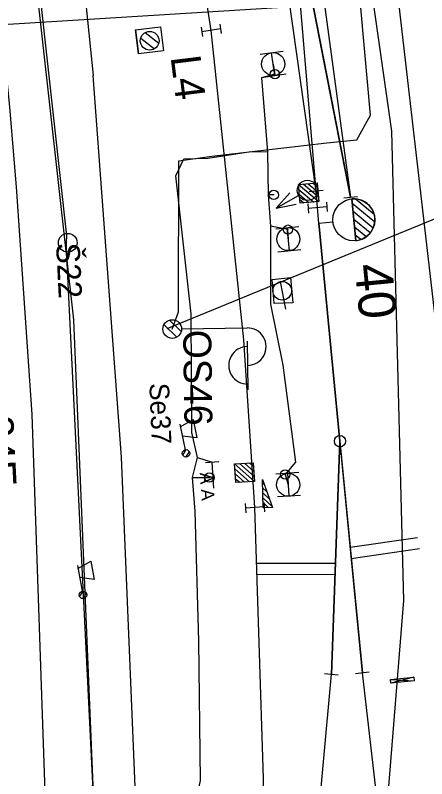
# Model space of a CAD drawing. Extents: x -545736 to -544888, y -1122892 to -1119128.
# Drawn here: x -545114.79 to -545092.81, y -1122018.02 to -1121977.2 of the extents above; entities that cross this region are included whole.
import ezdxf

# ---------------------------------------------------------------- set-up
doc = ezdxf.new("R2010")
doc.units = 0
for name, color, linetype in [('osvětlené plochy-hodnota-obrys', 7, 'Continuous'), ('Vrstva 1', 7, 'Continuous'), ('Vrstva 11 - Trakce', 7, 'Continuous'), ('Vrstva 12 - Trakce zaklady', 7, 'Continuous'), ('Vrstva 2', 7, 'Continuous'), ('Vrstva 25', 7, 'Continuous'), ('Vrstva 26', 7, 'Continuous'), ('Vrstva 27', 7, 'Continuous'), ('Vrstva 28 - zabzar', 7, 'Continuous'), ('Vrstva 3', 7, 'Continuous'), ('Vrstva 3 - Lisy - Pocitaci body', 7, 'Continuous'), ('Vrstva 31', 7, 'Continuous'), ('Vrstva 33', 7, 'Continuous'), ('Vrstva 35', 7, 'Continuous'), ('Vrstva 43', 7, 'Continuous'), ('Vrstva 44', 7, 'Continuous'), ('Vrstva 47', 7, 'Continuous'), ('Vrstva 6 - Navesti', 7, 'Continuous'), ('Vrstva 63', 7, 'Continuous'), ('Vrstva 7', 7, 'Continuous'), ('Vrstva 7 - Namezniky-vystroj', 7, 'Continuous')]:
    doc.layers.add(name, color=color, linetype=linetype)

msp = doc.modelspace()

# ---------------------------------------------------------------- linework, layer by layer
at = {"layer": 'osvětlené plochy-hodnota-obrys'}
for points in [[(-545114.36, -1122142.005), (-545095.834, -1122030.811), (-545094.039, -1122008.497), (-545094.672, -1121983.393), (-545097.737, -1121961.902), (-545099.42, -1121918.553), (-545101.285, -1121870.536), (-545123.71, -1121759.379), (-545130.296, -1121736.567), (-545147.419, -1121693.847), (-545162.352, -1121662.092), (-545176.655, -1121642.604), (-545199.404, -1121614.631), (-545212.209, -1121594.037), (-545225.557, -1121565.516)], [(-545115.194, -1122188.84), (-545115.464, -1122158.52), (-545110.116, -1122078.531), (-545109.516, -1122044.98), (-545111.654, -1121993.485), (-545115.876, -1121955.778), (-545121.955, -1121920.051), (-545160.528, -1121723.806), (-545171.589, -1121690.909), (-545189.933, -1121650.816), (-545214.916, -1121599.46)]]:
    msp.add_lwpolyline(points, dxfattribs=at)
at = {"layer": 'Vrstva 1'}
for p, q in [((-545098.003, -1121981.146), (-545100.055, -1121970.675)), ((-545096.872, -1121986.917), (-545098.003, -1121981.146))]:
    msp.add_line(p, q, dxfattribs=at)
for points in [[(-545113.887, -1121998.538), (-545114.726, -1121986.367), (-545115.084, -1121982.113), (-545116.437, -1121968.628), (-545118.368, -1121953.708), (-545121.658, -1121933.786), (-545126, -1121911.447), (-545130.401, -1121888.923), (-545134.741, -1121866.64), (-545139.463, -1121842.499)], [(-545134.071, -1121845.897), (-545128.577, -1121873.956), (-545119.95, -1121917.752), (-545116.436, -1121936.376), (-545113.726, -1121953.511), (-545111.671, -1121970.139), (-545110.636, -1121980.411)], [(-545105.433, -1122068.234), (-545100.293, -1122037.549), (-545100.056, -1122036.054), (-545097.904, -1122012.428), (-545097.443, -1121999.97), (-545098.568, -1121988.313), (-545098.643, -1121987.484), (-545098.717, -1121986.607), (-545100.055, -1121970.675), (-545101.391, -1121953.551)], [(-545109.904, -1122095.374), (-545105.593, -1122069.199), (-545105.433, -1122068.234), (-545103.019, -1122053.82), (-545101.945, -1122036.704), (-545101.525, -1122017.986), (-545101.985, -1122003.523), (-545102.577, -1121994.549), (-545104.325, -1121978.003), (-545107.499, -1121957.653)], [(-545109.904, -1122095.374), (-545108.096, -1122084.399), (-545107.422, -1122068.991), (-545107.109, -1122051.446), (-545107.678, -1122035.331), (-545108.288, -1122020.588), (-545109.122, -1122000.817), (-545110.636, -1121980.411)], [(-545086.277, -1122094.6), (-545087.736, -1122078.961), (-545089.571, -1122062.994), (-545090.744, -1122054.141), (-545092.357, -1122042.208), (-545094.068, -1122029.354), (-545095.393, -1122019.621), (-545096.247, -1122012.36), (-545098.568, -1121988.313)], [(-545113.063, -1122022.444), (-545113.115, -1122020.779), (-545113.887, -1121998.538)]]:
    msp.add_lwpolyline(points, dxfattribs=at)
at = {"layer": 'Vrstva 11 - Trakce'}
for p, q in [((-545107.849, -1121978.124), (-545107.129, -1121978.686)), ((-545108.085, -1121978.415), (-545107.355, -1121978.985))]:
    msp.add_line(p, q, dxfattribs=at)
msp.add_circle((-545107.61, -1121978.559), 0.5, dxfattribs=at)
at = {"layer": 'Vrstva 12 - Trakce zaklady'}
for p, q in [((-545108.362, -1121977.978), (-545107.026, -1121977.818)), ((-545106.867, -1121979.102), (-545108.202, -1121979.253))]:
    msp.add_line(p, q, dxfattribs=at)
for points in [[(-545108.202, -1121979.253), (-545108.362, -1121977.978), (-545107.026, -1121977.818), (-545106.867, -1121979.102), (-545108.202, -1121979.253)], [(-545107.026, -1121977.818), (-545107.026, -1121977.818), (-545106.867, -1121979.102), (-545106.867, -1121979.102)], [(-545108.362, -1121977.978), (-545108.362, -1121977.978), (-545108.202, -1121979.253), (-545108.202, -1121979.253)]]:
    msp.add_lwpolyline(points, dxfattribs=at)
at = {"layer": 'Vrstva 2'}
for p, q in [((-545098.717, -1121986.607), (-545103.4, -1121953.3)), ((-545101.391, -1121953.551), (-545096.872, -1121986.917)), ((-545098.343, -1121986.575), (-545099.091, -1121986.639)), ((-545097.245, -1121986.951), (-545096.499, -1121986.883)), ((-545096.81, -1121987.013), (-545096.594, -1121989.253)), ((-545096.594, -1121989.253), (-545096.81, -1121987.013)), ((-545095.586, -1121988.257), (-545096.785, -1121987.269)), ((-545095.616, -1121987.843), (-545096.624, -1121987.013)), ((-545095.67, -1121988.576), (-545096.744, -1121987.691)), ((-545095.827, -1121988.836), (-545096.704, -1121988.113)), ((-545098.568, -1121988.313), (-545097.821, -1121988.241)), ((-545096.046, -1121989.044), (-545096.663, -1121988.536)), ((-545096.336, -1121989.194), (-545096.622, -1121988.958)), ((-545097.443, -1121999.97), (-545096.247, -1122012.36)), ((-545098.277, -1122012.394), (-545097.531, -1122012.462)), ((-545095.875, -1122012.316), (-545096.619, -1122012.404))]:
    msp.add_line(p, q, dxfattribs=at)
for points in [[(-545103.4, -1121953.3), (-545100.055, -1121970.675), (-545098.003, -1121981.146), (-545096.872, -1121986.917), (-545100.055, -1121970.675)], [(-545098.717, -1121986.607), (-545100.055, -1121970.675), (-545101.391, -1121953.551)], [(-545098.568, -1121988.313), (-545097.443, -1121999.97), (-545097.904, -1122012.428)]]:
    msp.add_lwpolyline(points, dxfattribs=at)
for centre, radius in [((-545096.702, -1121988.133), 1.125), ((-545097.443, -1121999.97), 0.3)]:
    msp.add_circle(centre, radius, dxfattribs=at)
msp.add_arc((-545096.702, -1121988.133), 1.125, 275.5125, 95.5125, dxfattribs=at)
at = {"layer": 'Vrstva 25'}
for p, q in [((-545106.844, -1121993.742), (-545106.158, -1121994.409)), ((-545106.557, -1121993.499), (-545105.926, -1121994.112)), ((-545105.904, -1121993.968), (-545102.404, -1121993.917)), ((-545102.394, -1121994.617), (-545102.357, -1121997.217))]:
    msp.add_line(p, q, dxfattribs=at)
msp.add_circle((-545106.404, -1121993.975), 0.5, dxfattribs=at)
msp.add_circle((-545106.404, -1121993.975), 0.5, dxfattribs=at)
for centre, start, end in [((-545102.39, -1121994.917), 270.8271, 90.8271), ((-545102.388, -1121995.917), 90.1246, 271.5297)]:
    msp.add_arc(centre, 1, start, end, dxfattribs=at)
at = {"layer": 'Vrstva 26'}
for points in [[(-545106.404, -1121993.975), (-545106.061, -1121993.054), (-545106.047, -1121984.989), (-545104.296, -1121984.727), (-545098.144, -1121984.02), (-545096.547, -1121983.856), (-545095.817, -1121982.532), (-545096.984, -1121969.462), (-545095.362, -1121967.405)], [(-545106.047, -1121984.989), (-545104.296, -1121984.727), (-545098.144, -1121984.02), (-545096.547, -1121983.856)]]:
    msp.add_lwpolyline(points, dxfattribs=at)
at = {"layer": 'Vrstva 27'}
for p, q in [((-545100.917, -1121980.375), (-545100.923, -1121980.325)), ((-545100.978, -1121986.825), (-545100.982, -1121986.775)), ((-545100.218, -1121988.685), (-545100.222, -1121988.635)), ((-545104.418, -1122001.945), (-545104.422, -1122001.895)), ((-545100.371, -1122001.725), (-545100.369, -1122001.775))]:
    msp.add_line(p, q, dxfattribs=at)
for centre in [(-545100.92, -1121980.35), (-545100.98, -1121986.8), (-545100.22, -1121988.66), (-545100.37, -1122001.75), (-545104.42, -1122001.92)]:
    msp.add_circle(centre, 0.25, dxfattribs=at)
at = {"layer": 'Vrstva 28 - zabzar'}
for p, q in [((-545100.98, -1121986.8), (-545101.27, -1121986.8)), ((-545105.06, -1122000.85), (-545104.27, -1122001.1)), ((-545105.33, -1122001.91), (-545104.42, -1122001.92))]:
    msp.add_line(p, q, dxfattribs=at)
for points in [[(-545101.01, -1121979.81), (-545100.92, -1121980.35), (-545101.63, -1121980.55), (-545101.31, -1121984.5), (-545101.27, -1121986.8), (-545101.15, -1121988.47), (-545101.15, -1121992.65), (-545100.49, -1121995.91), (-545099.81, -1122001.09), (-545100.37, -1122001.75), (-545100.21, -1122002.3)], [(-545104.69, -1122037.85), (-545104.87, -1122035.26), (-545104.85, -1122032.88), (-545105.25, -1122026.5), (-545105.84, -1122024.56), (-545105.87, -1122022.8), (-545104.89, -1122018.11), (-545104.99, -1122010.67), (-545105.18, -1122003.72), (-545105.33, -1122001.91), (-545105.06, -1122000.85), (-545105.36, -1121999.5), (-545105.4, -1121993.17), (-545106.22, -1121985.78), (-545105.79, -1121984.88), (-545104.51, -1121984.83), (-545102.2, -1121984.49), (-545101.31, -1121984.5)], [(-545100.2, -1121989.17), (-545100.22, -1121988.66), (-545101.15, -1121988.47)]]:
    msp.add_lwpolyline(points, dxfattribs=at)
at = {"layer": 'Vrstva 3'}
for p, q in [((-545104.858, -1121977.833), (-545104.781, -1121978.327)), ((-545103.831, -1121977.926), (-545104.819, -1121978.08)), ((-545103.869, -1121977.679), (-545103.792, -1121978.173)), ((-545100.86, -1121987.504), (-545100.128, -1121986.695)), ((-545100.86, -1121987.504), (-545099.658, -1121986.826)), ((-545100.86, -1121987.504), (-545099.789, -1121987.296)), ((-545099.162, -1121987.276), (-545099.119, -1121987.774)), ((-545098.165, -1121987.191), (-545098.123, -1121987.689)), ((-545098.144, -1121987.44), (-545099.14, -1121987.525)), ((-545101.503, -1122003.241), (-545101.47, -1122003.74)), ((-545102.5, -1122003.306), (-545102.467, -1122003.805)), ((-545101.486, -1122003.49), (-545102.484, -1122003.556))]:
    msp.add_line(p, q, dxfattribs=at)
msp.add_circle((-545099.185, -1121986.561), 0.542, dxfattribs=at)
at = {"layer": 'Vrstva 3 - Lisy - Pocitaci body'}
for p, q in [((-545101.706, -1121979.286), (-545100.486, -1121979.114)), ((-545100.924, -1121980.42), (-545101.096, -1121979.2)), ((-545101.534, -1121980.506), (-545100.314, -1121980.334)), ((-545099.661, -1121986.252), (-545098.575, -1121987.158)), ((-545099.637, -1121986.516), (-545098.839, -1121987.182)), ((-545099.397, -1121986.228), (-545098.599, -1121986.894)), ((-545099.133, -1121986.204), (-545098.623, -1121986.63)), ((-545098.869, -1121986.18), (-545098.647, -1121986.366)), ((-545099.613, -1121986.78), (-545099.103, -1121987.206)), ((-545099.589, -1121987.044), (-545099.367, -1121987.23)), ((-545100.872, -1121988.616), (-545099.646, -1121988.498)), ((-545100.141, -1121989.783), (-545100.259, -1121988.557)), ((-545100.754, -1121989.842), (-545099.528, -1121989.724)), ((-545103.071, -1122001.187), (-545102.007, -1122002.119)), ((-545102.806, -1122001.169), (-545102.025, -1122001.854)), ((-545102.541, -1122001.152), (-545102.042, -1122001.59)), ((-545102.277, -1122001.135), (-545102.059, -1122001.325)), ((-545103.053, -1122001.451), (-545102.272, -1122002.136)), ((-545099.636, -1122001.645), (-545100.865, -1122001.726)), ((-545103.036, -1122001.716), (-545102.536, -1122002.154)), ((-545103.018, -1122001.981), (-545102.801, -1122002.171)), ((-545100.251, -1122001.685), (-545100.169, -1122002.915)), ((-545101.585, -1122002.196), (-545101.498, -1122002.278)), ((-545101.576, -1122002.461), (-545101.353, -1122002.671)), ((-545101.568, -1122002.726), (-545101.208, -1122003.064)), ((-545099.555, -1122002.874), (-545100.784, -1122002.955)), ((-545101.56, -1122002.992), (-545101.063, -1122003.458)), ((-545101.551, -1122003.256), (-545101.272, -1122003.518)), ((-545101.543, -1122003.521), (-545101.537, -1122003.527))]:
    msp.add_line(p, q, dxfattribs=at)
for points in [[(-545098.665, -1121986.162), (-545098.575, -1121987.158), (-545099.571, -1121987.248), (-545099.661, -1121986.252)], [(-545102.073, -1122001.121), (-545102.007, -1122002.119), (-545103.005, -1122002.185), (-545103.071, -1122001.187)]]:
    msp.add_lwpolyline(points, close=True, dxfattribs=at)
msp.add_lwpolyline([(-545101.59, -1122002.028), (-545101.043, -1122003.511), (-545101.543, -1122003.527), (-545101.59, -1122002.028)], dxfattribs=at)
for centre in [(-545101.011, -1121979.808), (-545100.201, -1121989.168), (-545100.209, -1122002.302)]:
    msp.add_circle(centre, 0.616, dxfattribs=at)
at = {"layer": 'Vrstva 31'}
msp.add_lwpolyline([(-545095.362, -1121967.405), (-545091.408, -1122001.644), (-545090.376, -1122001.911)], dxfattribs=at)
at = {"layer": 'Vrstva 33'}
for p, q in [((-545106.004, -1121999.057), (-545105.721, -1122000.426)), ((-545105.974, -1121999.204), (-545105.29, -1121998.808)), ((-545105.29, -1121998.808), (-545105.088, -1121999.788)), ((-545105.088, -1121999.788), (-545105.873, -1121999.694)), ((-545105.846, -1122000.713), (-545105.655, -1122000.422)), ((-545105.676, -1122000.819), (-545105.489, -1122000.534)), ((-545111.444, -1122006.77), (-545110.751, -1122006.39)), ((-545110.751, -1122006.39), (-545110.572, -1122007.373)), ((-545111.471, -1122006.622), (-545111.219, -1122007.997)), ((-545110.572, -1122007.373), (-545111.354, -1122007.262)), ((-545111.351, -1122008.28), (-545111.153, -1122007.994)), ((-545111.184, -1122008.391), (-545110.99, -1122008.111))]:
    msp.add_line(p, q, dxfattribs=at)
for centre in [(-545105.669, -1122000.62), (-545105.669, -1122000.62), (-545111.172, -1122008.192), (-545111.172, -1122008.192)]:
    msp.add_circle(centre, 0.2, dxfattribs=at)
at = {"layer": 'Vrstva 35'}
msp.add_lwpolyline([(-545105.79, -1121984.88), (-545104.51, -1121984.83), (-545102.2, -1121984.49), (-545101.31, -1121984.5)], dxfattribs=at)
at = {"layer": 'Vrstva 43'}
msp.add_line((-545100.337, -1121992.911), (-545100.623, -1121991.44), dxfattribs=at)
for centre, radius in [((-545111.987, -1121989.36), 0.5), ((-545100.528, -1121991.929), 0.498)]:
    msp.add_circle(centre, radius, dxfattribs=at)
at = {"layer": 'Vrstva 44'}
msp.add_lwpolyline([(-545145.881, -1122080.467), (-545110.994, -1122075.048), (-545110.527, -1122074.885), (-545110.524, -1122074.261), (-545109.816, -1122057.219), (-545109.784, -1122056.831), (-545109.776, -1122056.431), (-545110.644, -1122019.05), (-545110.681, -1122018.615), (-545110.652, -1122018.269), (-545112.055, -1121989.719), (-545112.056, -1121989.341), (-545112.028, -1121988.988), (-545115.846, -1121954.609), (-545115.954, -1121954.18), (-545116.046, -1121953.82), (-545122.306, -1121918.54), (-545122.337, -1121918.274), (-545121.996, -1121918.289), (-545097.226, -1121913.425), (-545096.722, -1121913.307), (-545096.631, -1121912.848), (-545094.158, -1121900.041)], dxfattribs=at)
at = {"layer": 'Vrstva 47'}
msp.add_line((-545101.069, -1121991.33), (-545100.09, -1121991.213), dxfattribs=at)
msp.add_lwpolyline([(-545100.09, -1121991.213), (-545099.953, -1121992.574), (-545100.951, -1121992.605), (-545101.069, -1121991.33)], dxfattribs=at)
msp.add_lwpolyline([(-545101.069, -1121991.33), (-545101.069, -1121991.33)], close=True, dxfattribs=at)
at = {"layer": 'Vrstva 6 - Navesti'}
for p, q in [((-545103.921, -1122001.077), (-545104.619, -1122001.123)), ((-545104.179, -1122002.483), (-545104.27, -1122001.1))]:
    msp.add_line(p, q, dxfattribs=at)
at = {"layer": 'Vrstva 63'}
for p, q in [((-545070.962, -1121974.942), (-545140.764, -1121979.274)), ((-545070.175, -1121978.964), (-545106.697, -1121993.96))]:
    msp.add_line(p, q, dxfattribs=at)
at = {"layer": 'Vrstva 7'}
for p, q in [((-545096.895, -1122005.646), (-545093.304, -1122005.122)), ((-545096.837, -1122006.244), (-545093.189, -1122005.711)), ((-545101.891, -1122006.485), (-545097.684, -1122006.496)), ((-545101.872, -1122007.085), (-545097.707, -1122007.096))]:
    msp.add_line(p, q, dxfattribs=at)
at = {"layer": 'Vrstva 7 - Namezniky-vystroj'}
msp.add_line((-545094.744, -1122012.705), (-545093.48, -1122012.783), dxfattribs=at)
msp.add_lwpolyline([(-545093.499, -1122012.584), (-545094.725, -1122012.904), (-545094.744, -1122012.705), (-545093.499, -1122012.584), (-545093.48, -1122012.783), (-545094.725, -1122012.904)], dxfattribs=at)

# ---------------------------------------------------------------- texts
at = {"layer": 'Vrstva 11 - Trakce'}
for s, rotation, p in [('L4', 277.0591, (-545106.495, -1121979.429)), ('34E', 272.858, (-545116.502, -1121998.64))]:
    msp.add_text(s, height=1.6, rotation=rotation, dxfattribs=at).set_placement(p)
at = {"layer": 'Vrstva 2'}
msp.add_text('40', height=2, rotation=275.5134, dxfattribs=at).set_placement((-545096.667, -1121990.556))
at = {"layer": 'Vrstva 25'}
msp.add_text('OS46', height=1.5, rotation=270.8271, dxfattribs=at).set_placement((-545105.825, -1121994.021))
at = {"layer": 'Vrstva 43'}
msp.add_text('Š22', height=1.25, rotation=272.8134, dxfattribs=at).set_placement((-545112.611, -1121989.391))
at = {"layer": 'Vrstva 6 - Navesti'}
for s, height, rotation, p in [('Se37', 1.05, 272.4155, (-545107.63, -1121996.88)), ('  A A ', 0.7, 273.7742, (-545104.968, -1122001.146))]:
    msp.add_text(s, height=height, rotation=rotation, dxfattribs=at).set_placement(p)

doc.saveas('drawing.dxf')
